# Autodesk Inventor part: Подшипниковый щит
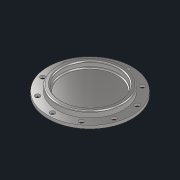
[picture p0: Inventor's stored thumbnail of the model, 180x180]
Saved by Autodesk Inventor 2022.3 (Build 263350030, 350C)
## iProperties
Created: 2022-08
Part Number: Подшипниковый щит
Material: Сталь 40ХНМА
Document SubType Name: Modeling
Designer: Карташов
Density: 7.85 g/cm^3
Appearance: С умеренной полировкой
Author: Карташов
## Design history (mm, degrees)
sketch "Эскиз1"
  geometry: L1 (0, 0)-(0, 34.001); L2 (45, -5)-(70, -5); L3 (70, -5)-(70, 0); L4 (70, 0)-(55, 0); L5 (55, 0)-(55, 8); L6 (53, 10)-(49, 10); L7 (47, 8)-(47, 2); L8 (45, 0)-(0, 0); L9 (45, -5)-(43, -7); L10 (43, -7)-(0, -7); L11 (0, -7)-(0, 0); A1 r 2 centre (45, 2) between (45, 0) and (47, 2); A2 r 2 centre (53, 8) between (55, 8) and (53, 10); A3 r 2 centre (49, 8) between (49, 10) and (47, 8); 4 further points
  constraints: 22 end point, 6 point on circle, 6 tangent, 5 horizontal, 4 point on line, 3 centre point, 3 vertical, 2 midpoint, 2 perpendicular
  dimensions: "d0" = 110 diameter of L5 point (0, 17); "d1" = 140 diameter of L3 L1; "d4" = 5 distance of L2.end L3.end; "d5" = 10 distance between parallel lines of L8 L6; "d6" = 8 distance of point (55, 10) point (47, 10); "d7" = 2 radius of A1; "d21" = 2 horizontal distance of L2.start L9.end; "d22" = 2 horizontal distance of L2.start L9.end; "d23" = 90 diameter of L2.start L1; "d24" = 2 radius of A2; "d25" = 2 radius of A3 (derived); "d26" = 17 distance from line of point (51, 10) L10
revolve "Вращение1" sketch "Эскиз1" stored, may be unused: angle "d9" = 90 deg
sketch "Эскиз2"
  geometry: C1 r 55 at (0, 0) reference; C2 r 70 at (0, 0) reference; 2 further points
  constraints: 1 vertical alignment
  dimensions: "d10" = 62.5 distance of point (0, 0) point (0, -62.5)
  node "Спроецированная петля1"
sketch "Эскиз3"
  geometry: 2 further points
hole "Отверстие1" sketch "Эскиз3" at (0, 62.5) diameter "d11" = 8; stored, may be unused: countersink angle "d15" = 90 deg, drill point angle "d17" = 0 deg; dims "d12" = 6, "d13" = 13, "d14" = 1, "d16" = 22.5
pattern_circular "Круговой массив1" dims angle "d19" = 360 deg
node "Твердое тело1"
